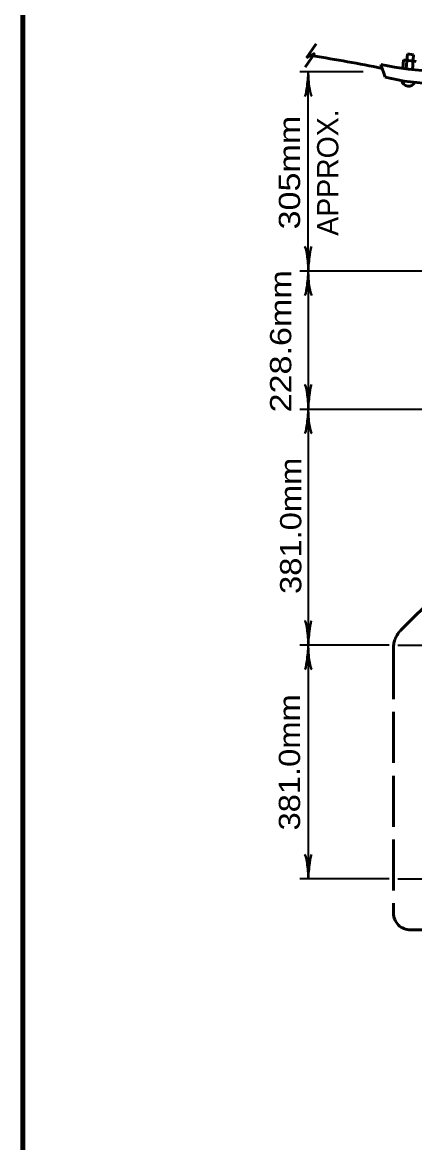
# Model space of a CAD drawing. Extents: x -35 to 821, y -10 to 534.
# Drawn here: x 22.7 to 78, y 232.3 to 390.4 of the extents above; entities that cross this region are included whole.
import ezdxf
from ezdxf.enums import TextEntityAlignment as Align

# ---------------------------------------------------------------- set-up
doc = ezdxf.new("R2010")
doc.units = 0
doc.header["$LTSCALE"] = 1.2
doc.linetypes.add('LONG_DASHED', pattern=[7.5, 6, -1.5])
doc.layers.add('1', color=7, linetype='Continuous', lineweight=35)

msp = doc.modelspace()

# ---------------------------------------------------------------- linework, layer by layer
at = {"layer": '1', "lineweight": 53}
for p, q in [((62.589, 384.055), (63.966, 386.021)), ((62.772, 385.374), (64.148, 387.34)), ((62.772, 385.374), (63.966, 386.021)), ((76.835, 383.84), (77.018, 385.932)), ((77.018, 385.932), (77.888, 385.763)), ((73.283, 384.427), (73.883, 382.627)), ((76.384, 383.851), (76.491, 385.075)), ((76.491, 385.075), (78.275, 384.834)), ((77.742, 383.668), (77.888, 385.763))]:
    msp.add_line(p, q, dxfattribs=at)
at = {"layer": '1'}
for p, q in [((70.798, 383.373), (61.829, 383.373)), ((63.029, 355.257), (63.029, 383.373)), ((80.156, 355.257), (61.829, 355.257)), ((61.829, 335.777), (115.883, 335.777)), ((74.456, 302.458), (61.829, 302.458)), ((75.656, 302.458), (86.756, 302.458)), ((74.456, 269.458), (61.829, 269.458)), ((75.656, 269.458), (84.11, 269.458))]:
    msp.add_line(p, q, dxfattribs=at)
at = {"layer": '1', "linetype": 'LONG_DASHED', "lineweight": 53}
for p, q in [((76.11, 304.583), (109.711, 338.184)), ((75.056, 302.037), (75.056, 264.658)), ((77.456, 262.257), (151.856, 262.257))]:
    msp.add_line(p, q, dxfattribs=at)
at = {"layer": '1', "lineweight": 158}
msp.add_lwpolyline([(814.384, 527.35), (22.684, 527.25), (22.784, 1.25)], dxfattribs=at)
at = {"layer": '1'}
msp.add_lwpolyline([(63.029, 355.257), (63.029, 335.777), (63.029, 302.458), (63.029, 269.458)], dxfattribs=at)
at = {"layer": '1', "lineweight": 53}
for centre, radius, start, end in [((36.395, 206.674), 181.022, 78.18089, 81.33006), ((81.083, 417.777), 34.25, 256.83593, 283.1638), ((81.083, 410.977), 29.25, 255.74997, 284.25003), ((77.196, 382.342), 0.986, 192.33045, 332.21364)]:
    msp.add_arc(centre, radius, start, end, dxfattribs=at)
at = {"layer": '1', "linetype": 'LONG_DASHED', "lineweight": 53}
for centre, radius, start, end in [((78.656, 302.037), 3.6, 135, 180), ((77.456, 264.658), 2.4, 180, 270)]:
    msp.add_arc(centre, radius, start, end, dxfattribs=at)
at = {"layer": '1', "lineweight": 40}
for centre, major_axis, ratio, start_param, end_param in [((62.775, 382.028), (0.211, 2.108), 0.07063, 3.1407148, 5.41811), ((62.775, 382.028), (0.211, 2.108), 0.07063, 3.1407148, 5.41811), ((63.36, 382.064), (-0.187, 2.143), 0.122415, 0.8963533, 3.1415927), ((63.36, 382.064), (-0.187, 2.143), 0.122415, 0.8963533, 3.1415927), ((62.697, 356.567), (0.187, -2.143), 0.122415, 0.8963533, 3.1415927), ((62.697, 356.567), (0.187, -2.143), 0.122415, 0.8963533, 3.1415927), ((63.283, 356.602), (-0.211, -2.108), 0.07063, 3.1407148, 5.41811), ((63.283, 356.602), (-0.211, -2.108), 0.07063, 3.1407148, 5.41811), ((62.775, 353.913), (0.211, 2.108), 0.07063, 3.1407148, 5.41811), ((62.775, 353.913), (0.211, 2.108), 0.07063, 3.1407148, 5.41811), ((63.36, 353.948), (-0.187, 2.143), 0.122415, 0.8963533, 3.1415927), ((63.36, 353.948), (-0.187, 2.143), 0.122415, 0.8963533, 3.1415927), ((62.697, 337.086), (0.187, -2.143), 0.122415, 0.8963533, 3.1415927), ((62.697, 337.086), (0.187, -2.143), 0.122415, 0.8963533, 3.1415927), ((63.283, 337.121), (-0.211, -2.108), 0.07063, 3.1407148, 5.41811), ((63.283, 337.121), (-0.211, -2.108), 0.07063, 3.1407148, 5.41811), ((62.775, 334.432), (0.211, 2.108), 0.07063, 3.1407148, 5.41811), ((62.775, 334.432), (0.211, 2.108), 0.07063, 3.1407148, 5.41811), ((63.36, 334.467), (-0.187, 2.143), 0.122415, 0.8963533, 3.1415927), ((63.36, 334.467), (-0.187, 2.143), 0.122415, 0.8963533, 3.1415927), ((62.697, 303.767), (0.187, -2.143), 0.122415, 0.8963533, 3.1415927), ((62.697, 303.767), (0.187, -2.143), 0.122415, 0.8963533, 3.1415927), ((63.283, 303.802), (-0.211, -2.108), 0.07063, 3.1407148, 5.41811), ((63.283, 303.802), (-0.211, -2.108), 0.07063, 3.1407148, 5.41811), ((62.775, 301.113), (0.211, 2.108), 0.07063, 3.1407148, 5.41811), ((62.775, 301.113), (0.211, 2.108), 0.07063, 3.1407148, 5.41811), ((63.36, 301.148), (-0.187, 2.143), 0.122415, 0.8963533, 3.1415927), ((63.36, 301.148), (-0.187, 2.143), 0.122415, 0.8963533, 3.1415927), ((62.697, 270.767), (0.187, -2.143), 0.122415, 0.8963533, 3.1415927), ((63.283, 270.802), (-0.211, -2.108), 0.07063, 3.1407148, 5.41811)]:
    msp.add_ellipse(centre, major_axis=major_axis, ratio=ratio, start_param=start_param, end_param=end_param, dxfattribs=at)

# ---------------------------------------------------------------- texts
at = {"layer": '1', "width": 1.2}
msp.add_text('305mm', height=3, rotation=90, dxfattribs=at).set_placement((61.874, 369.159), align=Align.CENTER)
at = {"layer": '1'}
msp.add_text('APPROX.', height=3, rotation=90, dxfattribs=at).set_placement((67.274, 369.159), align=Align.CENTER)
for s, width, p in [('228.6mm', 1.2, (60.629, 335.308)), ('381.0mm', 1.15, (62.05, 309.689)), ('381.0mm', 1.15, (61.872, 276.3))]:
    msp.add_text(s, height=3, rotation=90, dxfattribs=dict(at, width=width)).set_placement(p)

doc.saveas('drawing.dxf')
